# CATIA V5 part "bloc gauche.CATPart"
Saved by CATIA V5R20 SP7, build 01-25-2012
Part number: bloc patin gauche
Bounding box of the stored display mesh (mm): x -1.04 to 7.96, y -69.75 to -65.25, z 38.081 to 42.561
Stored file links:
  F:\Travaux\Modélisations\CFAO_2011\CFAO_2011_MMS\CFAO_2011_MMS_DONE\CFAO_2011_MMS_jboiteux\Catia\bloc gauche.CATPart
  U:\finthinkmotion\stepper.CATProduct
  F:\Travaux\Modélisations\CFAO_2011\CFAO_2011_MMS\CFAO_2011_MMS_DONE\CFAO_2011_MMS_jboiteux\Catia\support pied gauche.CATPart
  F:\Travaux\Modélisations\CFAO_2011\CFAO_2011_MMS\CFAO_2011_MMS_DONE\CFAO_2011_MMS_jboiteux\Catia\bati.CATPart
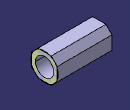
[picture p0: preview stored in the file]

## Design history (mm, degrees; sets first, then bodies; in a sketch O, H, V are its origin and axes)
Parameters
  rayontube = 9 mm {= External.royontubebati}
External parameters (linked from other documents)
  External.royontubebati = 9 mm
Set1
  DatumSurface1: linked copy from another document
  DatumCurve1: linked copy from another document
Body1 (main body)
  Sketch1 on face of DatumSurface1, origin (7.96, 0, 0), H (0, -1, 0), V (0, 0, 1)
    line L1 (69.6, 42.421) -> (65.4, 42.421)
    line L2 (65.4, 42.421) -> (65.4, 38.221)
    line L3 (65.4, 38.221) -> (69.6, 38.221)
    line L4 (69.6, 38.221) -> (69.6, 42.421)
    circle A1 centre (67.5, 40.321) radius 1.5
    point P5 (67.5, 40.321)
    reference projected circle E1 centre (67.5, 40.321) radius 1.5 from edge of DatumCurve1
    distance P5 L1 = 2.1 {= rayontube /9*2.1}
    distance L3 P5 = 2.1 {= rayontube /9*2.1}
    distance P5 L4 = 2.1 {= rayontube /9*2.1}
    distance L2 P5 = 2.1 {= rayontube /9*2.1}
    radius A1 = 1.5 {= rayontube /9*1.5}
    horizontal: L1 H, L3 H
    vertical: L2 V, L4 V
    concentricity: E1 A1
  Pad1: profile Sketch1, direction (-1, 0, 0), length 9 {= rayontube}
  Chamfer1: length 1 {= rayontube /9}, angle 45, on edge [face of Pad1 from Sketch1.L1 | face of Pad1 from Sketch1.L4]; edge [face of Pad1 from Sketch1.L2 | face of Pad1 from Sketch1.L1]; edge [face of Pad1 from Sketch1.L3 | face of Pad1 from Sketch1.L2]; edge [face of Pad1 from Sketch1.L4 | face of Pad1 from Sketch1.L3]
